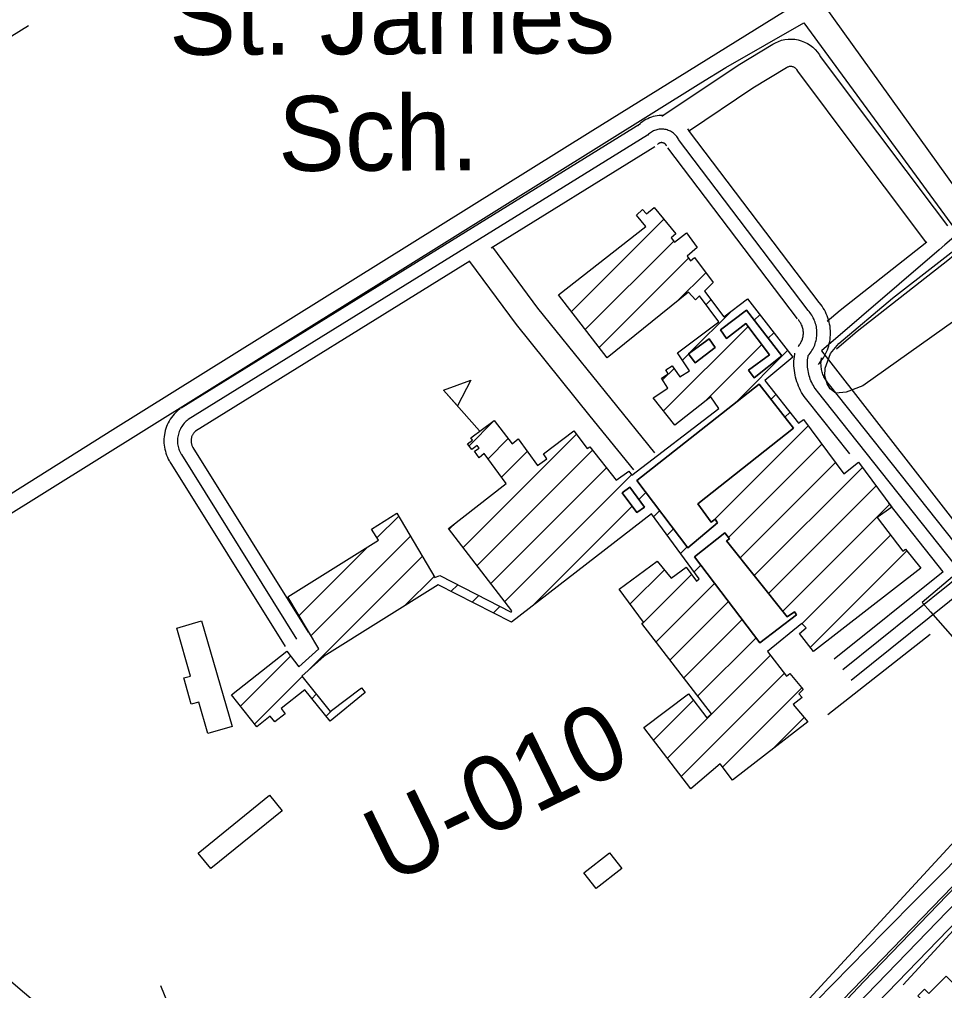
# Model space of a CAD drawing. Extents: x 3424494 to 3462436, y 522220 to 547718.
# Drawn here: x 3437311 to 3438335, y 541219 to 542295 of the extents above; entities that cross this region are included whole.
import ezdxf

# ---------------------------------------------------------------- set-up
doc = ezdxf.new("R2010")
doc.units = 0
for name, color, linetype in [('V-BLDG-IDEN', 7, 'Continuous'), ('V-BLDG-OTLN', 7, 'Continuous'), ('V-DTCH-CNTR', 7, 'Continuous'), ('V-RIVR-RANG-IDEN', 7, 'Continuous'), ('V-ROAD-CNTR', 7, 'Continuous'), ('V-SITE-OTLN', 7, 'Continuous'), ('V-SITE-VEGE', 7, 'Continuous'), ('V-TOPO-SHOR', 7, 'Continuous')]:
    doc.layers.add(name, color=color, linetype=linetype)

msp = doc.modelspace()

# ---------------------------------------------------------------- linework, layer by layer
at = {"layer": 'V-BLDG-OTLN'}
for p, q in [((3437922.3, 541971.2), (3438024.5, 542073.4)), ((3437937.6, 541951.2), (3438035.6, 542049.2)), ((3437953, 541931.2), (3438052.1, 542030.3)), ((3438039.9, 541982.8), (3438071.2, 542014.1)), ((3438071.4, 541978.9), (3438076.7, 541984.2)), ((3438053.5, 541925.7), (3438099.6, 541971.7)), ((3438124.8, 541961.6), (3438130.8, 541967.6)), ((3438024.3, 541861.1), (3438117.9, 541954.7)), ((3438140.2, 541941.6), (3438146.3, 541947.7)), ((3438069.2, 541870.7), (3438133.1, 541934.5)), ((3438045.2, 541917.4), (3438052, 541924.1)), ((3438104.9, 541871), (3438161.7, 541927.8)), ((3438023.3, 541895.4), (3438036, 541908.1)), ((3437820.5, 541839), (3437780.9, 541884.1)), ((3438143.2, 541873.9), (3438148.6, 541879.3)), ((3438158.7, 541854.1), (3438164.2, 541859.5)), ((3437809, 541822.6), (3437836.8, 541850.4)), ((3438080.5, 541740.5), (3438184.4, 541844.4)), ((3437802.5, 541710), (3437927.9, 541835.4)), ((3437830, 541808.2), (3437852.2, 541830.4)), ((3437817.9, 541690), (3437945.5, 541817.7)), ((3437844.9, 541787.8), (3437873.4, 541816.3)), ((3438096.1, 541720.8), (3438199.4, 541824.1)), ((3437833.2, 541670), (3437961.1, 541797.9)), ((3438109, 541698.3), (3438214.5, 541803.8)), ((3438124.8, 541678.7), (3438244.4, 541798.3)), ((3437848.6, 541650), (3437988.8, 541790.2)), ((3438140.5, 541659.1), (3438259.6, 541778.2)), ((3437996.9, 541763), (3438004.6, 541770.7)), ((3437879.1, 541645.2), (3437989.6, 541755.7)), ((3438062.5, 541757.9), (3438065.5, 541760.9)), ((3438156.2, 541639.5), (3438274.7, 541758)), ((3437707.1, 541720.6), (3437731.1, 541744.7)), ((3438013.2, 541744), (3438019.9, 541750.6)), ((3437787.1, 541730), (3437794.7, 541737.6)), ((3438028.2, 541723.6), (3438035.2, 541730.6)), ((3437634.1, 541612.3), (3437744.2, 541722.4)), ((3438177.7, 541625.6), (3438275.7, 541723.5)), ((3437620.9, 541634.5), (3437696.9, 541710.5)), ((3438043.2, 541703.2), (3438050.5, 541710.5)), ((3437630.5, 541573.4), (3437757.3, 541700.1)), ((3438186.7, 541599.3), (3438293.7, 541706.3)), ((3438058.1, 541682.8), (3438065.5, 541690.2)), ((3437737.7, 541645.2), (3437770.3, 541677.8)), ((3437987.4, 541647.4), (3438025.2, 541685.2)), ((3438000.7, 541625.3), (3438055.3, 541680)), ((3437789, 541661.2), (3437796.6, 541668.7)), ((3438016.1, 541605.4), (3438080.8, 541670.1)), ((3437812.5, 541649.3), (3437819.9, 541656.7)), ((3437836, 541637.4), (3437843.2, 541644.7)), ((3438031.5, 541585.4), (3438096.1, 541650)), ((3438046.9, 541565.5), (3438111.4, 541630)), ((3438062.3, 541545.5), (3438126.7, 541609.9)), ((3438028.6, 541476.5), (3438142.6, 541590.5)), ((3437555.9, 541534.1), (3437611.5, 541589.7)), ((3438044, 541456.5), (3438158.2, 541570.7)), ((3437571.5, 541514.4), (3437624.2, 541567.1)), ((3437635, 541542.5), (3437639.9, 541547.4)), ((3438089.7, 541466.8), (3438177.4, 541554.5)), ((3438013.3, 541496.5), (3438057.4, 541540.7)), ((3437650.8, 541523), (3437658.7, 541530.9)), ((3438144.8, 541486.6), (3438179.9, 541521.7))]:
    msp.add_line(p, q, dxfattribs=at)
for points in [[(3437774.7, 541668.4), (3437648.5, 541589.4), (3437623.9, 541567.5), (3437655.2, 541528.2), (3437690.1, 541554.5), (3437694, 541549.3), (3437655.2, 541517.6), (3437627.2, 541552.2), (3437601, 541531.5), (3437605.5, 541525.8), (3437593.9, 541516.7), (3437588.9, 541523), (3437574, 541511.2), (3437546.1, 541546.6), (3437607.4, 541595.1), (3437620.7, 541577.6), (3437642.9, 541597.6), (3437608.5, 541655.4), (3437708.8, 541717.9), (3437701, 541730.3), (3437729.2, 541747.9), (3437771, 541676.7), (3437776.5, 541679), (3437855.6, 541638.3), (3437856.4, 541639.9), (3437786.3, 541731), (3437850.1, 541780.7), (3437825.8, 541814), (3437820.3, 541809.3), (3437815.2, 541816.4), (3437820.3, 541820), (3437818, 541822.7), (3437812, 541818.4), (3437807.3, 541824.8), (3437812.9, 541828.7), (3437810.9, 541831.4), (3437836.7, 541850.6), (3437856.6, 541824.5), (3437863.4, 541830), (3437884.9, 541800.7), (3437895.2, 541808.1), (3437891.4, 541813.4), (3437925.1, 541839.1), (3437939.9, 541819.3), (3437942.7, 541821.3), (3437971.7, 541784.4), (3437985.9, 541794.2), (3437989.1, 541789.9), (3438085.7, 541863.9), (3438076.7, 541876.5), (3438036.7, 541845.2), (3438012.8, 541875.7), (3438029.1, 541886.3), (3438022, 541897.3), (3438029.4, 541902), (3438026.8, 541906.4), (3438033.9, 541911.1), (3438042.5, 541898.8), (3438053.2, 541905.5), (3438039.9, 541925.3), (3438085.5, 541959.7), (3438064.3, 541988.6), (3438059.7, 541984.1), (3438052.1, 541992.6), (3437961.8, 541919.8), (3437908.2, 541989.5), (3438004.8, 542065.1), (3437994.2, 542077.8), (3438001.2, 542084.2), (3438005.3, 542079.3), (3438014, 542086.3), (3438037.9, 542057), (3438032.8, 542052.7), (3438036.6, 542047.9), (3438049.8, 542058.1), (3438061.5, 542041.9), (3438050.4, 542032.5), (3438054.3, 542027.3), (3438058.7, 542030.8), (3438079.4, 542003.1), (3438069.5, 541993.7), (3438091, 541965.2), (3438117.2, 541985.2), (3438167.3, 541920.6), (3438136.4, 541894.7), (3438173.6, 541847.6), (3438179.1, 541851.5), (3438223.8, 541791.3), (3438240, 541804.2), (3438277.2, 541754.7), (3438260.9, 541743), (3438289.1, 541705.7), (3438292.3, 541708.1), (3438309.1, 541687.1), (3438190.3, 541594.7), (3438174.8, 541614.6), (3438182.2, 541621.1), (3438177.5, 541625.9), (3438139.4, 541594.6), (3438160.6, 541567.6), (3438164.1, 541570.4)], [(3438164.1, 541570.4), (3438179, 541552.5), (3438173.9, 541547.8), (3438177.8, 541543.9), (3438167.9, 541536), (3438183.9, 541517), (3438100.7, 541452.4), (3438087, 541470.2), (3438054.5, 541442.8), (3438002.5, 541510.5), (3438052, 541547.7), (3438072.3, 541521.3), (3438077.5, 541525.9), (3438000.4, 541625.7), (3438002.3, 541627.3), (3437975.3, 541663.7), (3438017.3, 541694.7), (3438032.9, 541676), (3438049.2, 541688.2), (3438060.7, 541672.7), (3438063.7, 541675.1), (3438010.9, 541747.1), (3437856, 541627.3), (3437774.7, 541668.4)]]:
    msp.add_lwpolyline(points, dxfattribs=at)
for points in [[(3438087.4, 541951), (3438116.3, 541972.6), (3438155.1, 541922.2), (3438124.6, 541897.6), (3438118.3, 541906.3), (3438141.7, 541923.1), (3438115.4, 541958), (3438094.1, 541941.1)], [(3438087.4, 541951), (3438094.1, 541941.1), (3438115.4, 541958), (3438141.7, 541923.1), (3438118.3, 541906.3), (3438124.6, 541897.6), (3438155.1, 541922.2), (3438116.3, 541972.6)], [(3438051.8, 541924.4), (3438059.2, 541914.2), (3438081.4, 541931.3), (3438074.7, 541940.8)], [(3438051.8, 541924.4), (3438074.7, 541940.8), (3438081.4, 541931.3), (3438059.2, 541914.2)], [(3437780.9, 541884.1), (3437811, 541895.2), (3437796.2, 541866.7)], [(3438051.3, 541709.4), (3437994.6, 541783.9), (3438130.1, 541890.8), (3438168, 541842.1), (3438062.3, 541758.3), (3438077.1, 541738.1), (3438081.5, 541741.2), (3438084.2, 541737.3)], [(3438051.3, 541709.4), (3438084.2, 541737.3), (3438081.5, 541741.2), (3438077.1, 541738.1), (3438062.3, 541758.3), (3438168, 541842.1), (3438130.1, 541890.8), (3437994.6, 541783.9)], [(3437987, 541776.5), (3438003.1, 541754.7), (3437994.7, 541748.8), (3437978.6, 541770.3)], [(3437987, 541776.5), (3437978.6, 541770.3), (3437994.7, 541748.8), (3438003.1, 541754.7)], [(3438058.4, 541699.5), (3438092, 541726.2), (3438097.2, 541719.5), (3438094, 541717.1), (3438161.3, 541633.1), (3438169.1, 541638.6), (3438171.6, 541635.4), (3438130.8, 541604.5)], [(3438058.4, 541699.5), (3438130.8, 541604.5), (3438171.6, 541635.4), (3438169.1, 541638.6), (3438161.3, 541633.1), (3438094, 541717.1), (3438097.2, 541719.5), (3438092, 541726.2)], [(3437513, 541628.6), (3437546.7, 541511.7), (3437519.8, 541503.9), (3437509.8, 541538.7), (3437501.5, 541536.3), (3437493.1, 541565.4), (3437500.8, 541567.6), (3437485.5, 541620.7)], [(3437602, 541418.5), (3437523.3, 541354.4), (3437509.2, 541371.6), (3437588, 541435.8)], [(3437978.1, 541354.4), (3437949.7, 541332.4), (3437936.2, 541349.8), (3437964.6, 541371.8)], [(3438357.3, 541215.5), (3438316.6, 541174.5), (3438303.7, 541187.3), (3438308.8, 541192.5), (3438304, 541197.2), (3438313.1, 541206.4), (3438305.9, 541213.6), (3438313.2, 541220.9), (3438318, 541216), (3438337.3, 541235.4)]]:
    msp.add_lwpolyline(points, close=True, dxfattribs=at)
at = {"layer": 'V-DTCH-CNTR'}
for points in [[(3438361.8, 541378.8), (3438334.2, 541350.6), (3438306.4, 541322.6), (3438268.5, 541284.5), (3438230.8, 541246.1), (3438193.3, 541207.6)], [(3437541.4, 541078.5), (3437538.5, 541085.9), (3437535.3, 541093.2), (3437532, 541100.5), (3437528.4, 541107.6), (3437524.6, 541114.7), (3437520.6, 541121.6), (3437516.4, 541128.4), (3437510.7, 541137.6), (3437505.2, 541146.9), (3437499.9, 541156.3), (3437494.8, 541165.8), (3437489.8, 541175.4), (3437485, 541185.1), (3437480.4, 541194.9), (3437476, 541204.7), (3437471.8, 541214.7), (3437467.8, 541224.7)]]:
    msp.add_lwpolyline(points, dxfattribs=at)
at = {"layer": 'V-ROAD-CNTR'}
for points in [[(3438022.6, 542187.4), (3438107.1, 542244), (3438145.3, 542267.2), (3438148.1, 542268.7), (3438151.5, 542270.2), (3438155, 542271.4), (3438158.6, 542272.2), (3438162.2, 542272.6), (3438165.9, 542272.7), (3438169.6, 542272.5), (3438173.2, 542271.8), (3438176.8, 542270.9), (3438180.2, 542269.5), (3438183.5, 542267.9), (3438186.6, 542265.9), (3438189.5, 542263.7), (3438192.2, 542261.2), (3438194.6, 542258.4), (3438196.8, 542255.4), (3438197.8, 542253.6), (3438261, 542168.8), (3438323.9, 542085.5), (3438338.7, 542065.9)], [(3438051.8, 542170.8), (3438123.3, 542218.7), (3438160.5, 542241.3), (3438161.5, 542241.9), (3438162.2, 542242.2), (3438162.9, 542242.4), (3438163.7, 542242.6), (3438164.4, 542242.7), (3438165.2, 542242.7), (3438165.9, 542242.6), (3438166.7, 542242.5), (3438167.4, 542242.3), (3438168.1, 542242), (3438168.8, 542241.7), (3438169.4, 542241.3), (3438170, 542240.8), (3438170.6, 542240.3), (3438171.1, 542239.8), (3438171.5, 542239.1), (3438172.7, 542237.1), (3438237, 542150.8), (3438299.9, 542067.5), (3438315.2, 542047.3)], [(3438616.9, 542239.7), (3438454, 542118.5), (3438345.3, 542032.9), (3438338.9, 542027.8), (3438238.6, 541948.9), (3438218.7, 541932.1), (3438215.8, 541929.6)], [(3438024.6, 542188), (3438024, 542188.1), (3438021.8, 542188.1), (3438019.6, 542188), (3438017.4, 542187.8), (3438015.2, 542187.4), (3438013, 542186.9), (3438010.9, 542186.3), (3438008.8, 542185.5), (3438006.8, 542184.6), (3438004.8, 542183.6), (3438002.9, 542182.5), (3438001, 542181.3), (3437999.3, 542179.9), (3437997.6, 542178.4), (3437996.1, 542177), (3437995.7, 542176.6)], [(3437998.8, 542179.1), (3437490.3, 541864.2)], [(3438041, 542161.6), (3438040.4, 542162.7), (3438039.7, 542163.8), (3438038.9, 542164.9), (3438038.1, 542165.9), (3438037.2, 542166.8), (3438036.2, 542167.7), (3438035.2, 542168.6), (3438034.2, 542169.3), (3438033.1, 542170), (3438032, 542170.7), (3438030.8, 542171.2), (3438029.6, 542171.7), (3438028.4, 542172.2), (3438027.1, 542172.5), (3438025.9, 542172.8), (3438024.6, 542173), (3438023.3, 542173.1), (3438022, 542173.1), (3438020.7, 542173), (3438019.4, 542172.9), (3438018.1, 542172.7), (3438016.8, 542172.4), (3438015.6, 542172), (3438014.4, 542171.6), (3438013.2, 542171.1), (3438012, 542170.5), (3438010.9, 542169.8), (3438009.8, 542169.1), (3438008.8, 542168.3), (3438007.8, 542167.4), (3438006.9, 542166.5), (3438006.7, 542166.3)], [(3438054.1, 542168.8), (3438053.3, 542170.4), (3438052.1, 542172.3), (3438051.3, 542173.3)], [(3438196.5, 541981.2), (3438052.9, 542170.6)], [(3438006.7, 542166.3), (3437498.2, 541851.5)], [(3438184.5, 541972.1), (3438041, 542161.6)], [(3438014.6, 542153.6), (3437833.5, 542041.4)], [(3438027.8, 542154.4), (3438027.4, 542155.1), (3438027.2, 542155.4), (3438027, 542155.7), (3438026.8, 542156), (3438026.5, 542156.3), (3438026.2, 542156.5), (3438026, 542156.8), (3438025.7, 542157), (3438025.3, 542157.2), (3438025, 542157.4), (3438024.7, 542157.6), (3438024.3, 542157.7), (3438024, 542157.8), (3438023.6, 542157.9), (3438023.2, 542158), (3438022.9, 542158), (3438022.5, 542158.1), (3438022.1, 542158.1), (3438021.7, 542158.1), (3438021.4, 542158), (3438021, 542158), (3438020.6, 542157.9), (3438020.3, 542157.8), (3438019.9, 542157.7), (3438019.6, 542157.5), (3438019.2, 542157.3), (3438018.9, 542157.1), (3438018.6, 542156.9), (3438018.3, 542156.7), (3438018, 542156.5), (3438017.6, 542156.1), (3438017.6, 542156)], [(3438172.6, 541963.1), (3438029, 542152.5)], [(3438896.3, 542102.6), (3438854.4, 542082.1), (3438222.7, 541574.5)], [(3438902.2, 542088.8), (3438862.5, 542069.4), (3438232.1, 541562.8)], [(3437835, 542042.4), (3437884.9, 541975), (3437966.1, 541874.3), (3438014.4, 541814.7)], [(3438315.8, 542047.9), (3438219.7, 541972.2), (3438205.3, 541960)], [(3437809.9, 542026.8), (3437506.1, 541838.7)], [(3437809.4, 542026.5), (3437861.2, 541956.7), (3437942.8, 541855.4), (3437991.1, 541795.8)], [(3438195.8, 541912.6), (3438197.1, 541914.1), (3438198.6, 541916), (3438200, 541918), (3438201.4, 541920), (3438202.6, 541922.1), (3438203.7, 541924.2), (3438204.7, 541926.4), (3438205.7, 541928.6), (3438206.5, 541930.9), (3438207.2, 541933.2), (3438207.8, 541935.6), (3438208.3, 541937.9), (3438208.7, 541940.3), (3438208.9, 541942.7), (3438209.1, 541945.1), (3438209.1, 541947.5), (3438209.1, 541949.9), (3438208.9, 541952.4), (3438208.6, 541954.8), (3438208.2, 541957.1), (3438207.7, 541959.5), (3438207.1, 541961.8), (3438206.3, 541964.1), (3438205.5, 541966.4), (3438204.5, 541968.6), (3438203.5, 541970.8), (3438202.4, 541972.9), (3438201.1, 541975), (3438199.8, 541977), (3438198.3, 541979), (3438196.8, 541980.8), (3438195.8, 541982)], [(3438184.5, 541922.4), (3438185.6, 541923.7), (3438186.7, 541925.1), (3438187.7, 541926.5), (3438188.6, 541927.9), (3438189.5, 541929.4), (3438190.3, 541930.9), (3438191, 541932.4), (3438191.7, 541934), (3438192.2, 541935.7), (3438192.7, 541937.3), (3438193.2, 541939), (3438193.5, 541940.6), (3438193.8, 541942.3), (3438194, 541944), (3438194.1, 541945.7), (3438194.1, 541947.5), (3438194.1, 541949.2), (3438194, 541950.9), (3438193.7, 541952.6), (3438193.5, 541954.3), (3438193.1, 541956), (3438192.7, 541957.6), (3438192.1, 541959.3), (3438191.5, 541960.9), (3438190.9, 541962.4), (3438190.1, 541964), (3438189.3, 541965.5), (3438188.4, 541967), (3438187.5, 541968.4), (3438186.5, 541969.8), (3438185.4, 541971.1), (3438184.5, 541972.1)], [(3438955.7, 541963.9), (3438831.4, 541837.9), (3437779.6, 540751.2), (3436981.6, 539923.1), (3436419.1, 539354.6)], [(3438173.2, 541932.3), (3438174.1, 541933.3), (3438174.7, 541934.1), (3438175.3, 541935), (3438175.9, 541935.8), (3438176.4, 541936.7), (3438176.8, 541937.6), (3438177.3, 541938.5), (3438177.7, 541939.4), (3438178, 541940.4), (3438178.3, 541941.4), (3438178.6, 541942.3), (3438178.8, 541943.3), (3438178.9, 541944.4), (3438179, 541945.4), (3438179.1, 541946.4), (3438179.1, 541947.4), (3438179.1, 541948.4), (3438179, 541949.4), (3438178.9, 541950.4), (3438178.7, 541951.4), (3438178.5, 541952.4), (3438178.2, 541953.4), (3438177.9, 541954.4), (3438177.6, 541955.3), (3438177.2, 541956.3), (3438176.8, 541957.2), (3438176.3, 541958.1), (3438175.7, 541959), (3438175.2, 541959.8), (3438174.6, 541960.6), (3438173.9, 541961.4), (3438173.3, 541962.2)], [(3438956.6, 541943.4), (3438842.1, 541827.4), (3437790.4, 540740.8), (3436992.3, 539912.6), (3435795.3, 538702.9), (3434822.5, 537711.3), (3433638.5, 536500.9), (3432411.7, 535256.8), (3431892.4, 534722)], [(3438182.9, 541873.3), (3438181.5, 541875.1), (3438180, 541877.2), (3438178.5, 541879.4), (3438177.2, 541881.6), (3438176, 541883.8), (3438174.8, 541886.1), (3438173.7, 541888.5), (3438172.8, 541890.9), (3438171.9, 541893.3), (3438171.1, 541895.8), (3438170.5, 541898.3), (3438169.9, 541900.8), (3438169.5, 541903.4), (3438169.1, 541905.9), (3438168.8, 541908.5), (3438168.7, 541911.1), (3438168.6, 541913.6), (3438168.7, 541916.2), (3438168.9, 541918.8), (3438169.1, 541921.4), (3438169.5, 541923.8), (3438169.7, 541925)], [(3438194.7, 541882.6), (3438193.5, 541884.2), (3438192.3, 541885.8), (3438191.2, 541887.4), (3438190.2, 541889.1), (3438189.2, 541890.8), (3438188.4, 541892.6), (3438187.5, 541894.4), (3438186.8, 541896.2), (3438186.1, 541898.1), (3438185.6, 541900), (3438185.1, 541901.9), (3438184.6, 541903.8), (3438184.3, 541905.7), (3438184, 541907.7), (3438183.8, 541909.7), (3438183.7, 541911.6), (3438183.6, 541913.6), (3438183.7, 541915.6), (3438183.8, 541917.5), (3438184, 541919.5), (3438184.3, 541921.5), (3438184.5, 541922.4)], [(3438206.5, 541891.9), (3438205.4, 541893.2), (3438204.6, 541894.3), (3438203.9, 541895.4), (3438203.2, 541896.6), (3438202.5, 541897.8), (3438201.9, 541899), (3438201.3, 541900.3), (3438200.8, 541901.5), (3438200.4, 541902.8), (3438200, 541904.1), (3438199.6, 541905.4), (3438199.3, 541906.8), (3438199.1, 541908.1), (3438198.9, 541909.5), (3438198.8, 541910.8), (3438198.7, 541912.2), (3438198.6, 541913.6), (3438198.7, 541914.9), (3438198.8, 541916.3), (3438198.9, 541917.7), (3438199.1, 541919.1), (3438199.2, 541919.8)], [(3438357.3, 541701.9), (3438206.4, 541891.9)], [(3438354.9, 541680.8), (3438194.7, 541882.6)], [(3438230.5, 541813.4), (3438182.9, 541873.3)], [(3437489.1, 541863.4), (3437487.5, 541862.2), (3437485.8, 541860.7), (3437484.1, 541859.1), (3437482.5, 541857.4), (3437481, 541855.7), (3437479.6, 541853.8), (3437478.3, 541851.9), (3437477.1, 541849.9), (3437476, 541847.9), (3437475, 541845.8), (3437474.1, 541843.7), (3437473.4, 541841.5), (3437472.7, 541839.3), (3437472.2, 541837), (3437471.8, 541834.8), (3437471.5, 541832.5), (3437471.3, 541830.2), (3437471.2, 541827.8), (3437471.3, 541825.5), (3437471.5, 541823.2), (3437471.8, 541820.9), (3437472.2, 541818.7), (3437472.8, 541816.4), (3437473.4, 541814.2), (3437474.2, 541812), (3437475.1, 541809.9), (3437476.1, 541807.8), (3437477.2, 541805.9), (3437477.7, 541805)], [(3437498.2, 541851.5), (3437497, 541850.5), (3437495.8, 541849.6), (3437494.7, 541848.5), (3437493.7, 541847.4), (3437492.7, 541846.2), (3437491.8, 541845), (3437490.9, 541843.8), (3437490.1, 541842.5), (3437489.4, 541841.1), (3437488.7, 541839.7), (3437488.2, 541838.3), (3437487.7, 541836.9), (3437487.2, 541835.4), (3437486.9, 541833.9), (3437486.6, 541832.4), (3437486.4, 541830.9), (3437486.3, 541829.4), (3437486.2, 541827.9), (3437486.3, 541826.4), (3437486.4, 541824.8), (3437486.6, 541823.3), (3437486.9, 541821.8), (3437487.3, 541820.4), (3437487.7, 541818.9), (3437488.2, 541817.5), (3437488.8, 541816), (3437489.5, 541814.7), (3437490.2, 541813.3), (3437490.6, 541812.7)], [(3437507.4, 541839.6), (3437506.5, 541838.9), (3437505.9, 541838.4), (3437505.4, 541837.9), (3437504.9, 541837.4), (3437504.4, 541836.8), (3437503.9, 541836.2), (3437503.5, 541835.6), (3437503.1, 541835), (3437502.8, 541834.3), (3437502.5, 541833.7), (3437502.2, 541833), (3437501.9, 541832.3), (3437501.7, 541831.6), (3437501.6, 541830.9), (3437501.4, 541830.1), (3437501.3, 541829.4), (3437501.3, 541828.7), (3437501.3, 541827.9), (3437501.3, 541827.2), (3437501.3, 541826.5), (3437501.4, 541825.7), (3437501.6, 541825), (3437501.7, 541824.3), (3437502, 541823.6), (3437502.2, 541822.9), (3437502.5, 541822.2), (3437502.8, 541821.5), (3437503.2, 541820.8), (3437503.4, 541820.4)], [(3437503.3, 541820.7), (3437630.8, 541616.2)], [(3437490.6, 541812.7), (3437618, 541608.2)], [(3437477.8, 541804.8), (3437605.3, 541600.3)], [(3438333.9, 541683.1), (3438273.6, 541759.1)], [(3438333.9, 541683.1), (3438213.3, 541586.2)], [(3438429.1, 541379.1), (3437801.2, 540730.4), (3437003.1, 539902.1), (3436441.5, 539334.6)]]:
    msp.add_lwpolyline(points, dxfattribs=at)
at = {"layer": 'V-SITE-OTLN'}
msp.add_lwpolyline([(3438093.1, 542241.3), (3438179.5, 542290.9), (3438350.3, 542057.5), (3438335.8, 542045), (3438329.6, 542039.6), (3438199.3, 541927.6), (3438374.2, 541702.8), (3438348.9, 541681.5), (3438310.5, 541649.1), (3438320, 541638.7), (3438447.3, 541494.1), (3437806.2, 540798.8), (3436951, 541528.5), (3438065.6, 542224.2)], close=True, dxfattribs=at)
at = {"layer": 'V-SITE-VEGE'}
msp.add_lwpolyline([(3438721.1, 542330.3), (3438739.6, 542341.6), (3438745.5, 542343.1), (3438750.6, 542341.1), (3438756.4, 542334.8), (3438760.3, 542325.8), (3438761, 542314.8), (3438753, 542291.7), (3438729.7, 542256.9), (3438550.4, 542105.7), (3438245.1, 541889), (3438226.3, 541882), (3438214.9, 541880.9), (3438208.6, 541885.7), (3438205.5, 541891.2), (3438202.8, 541899.8), (3438203.3, 541908.4), (3438209.2, 541924.5), (3438218.3, 541935.8), (3438277.8, 541986.1), (3438555.6, 542201.8), (3438707.3, 542321)], close=True, dxfattribs=at)
at = {"layer": 'V-TOPO-SHOR'}
for p, q in [((3438319.5, 541613.5), (3438206.3, 541524.7)), ((3438345.4, 541286.3), (3438289.5, 541225.5))]:
    msp.add_line(p, q, dxfattribs=at)
for points in [[(3438612.9, 542279.4), (3438359.2, 542091.4), (3438192.1, 542324.8), (3437942.9, 542169.8), (3437414.7, 541840.2), (3436924.1, 541531.6), (3436750.5, 541682), (3436582.6, 541826.3)], [(3437321.4, 542287.3), (3436932.5, 542046.3), (3436609.3, 541841.8)], [(3438472, 541463.3), (3438246, 541229.3), (3437950.3, 540915.7)]]:
    msp.add_lwpolyline(points, dxfattribs=at)

# ---------------------------------------------------------------- texts
at = {"layer": 'V-BLDG-IDEN'}
for s, p in [('St. James', (3437477.1, 542255.2)), ('Sch.', (3437597.8, 542126.7))]:
    msp.add_text(s, height=83, rotation=0.2224, dxfattribs=at).set_placement(p)
at = {"layer": 'V-RIVR-RANG-IDEN'}
msp.add_text('U-010', height=83, rotation=25.9423, dxfattribs=at).set_placement((3437720.8, 541336.1))

doc.saveas('drawing.dxf')
